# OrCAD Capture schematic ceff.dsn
size A; title: Discrete Negative Linear Regulator; rev: 1.0; note: PROJ-001
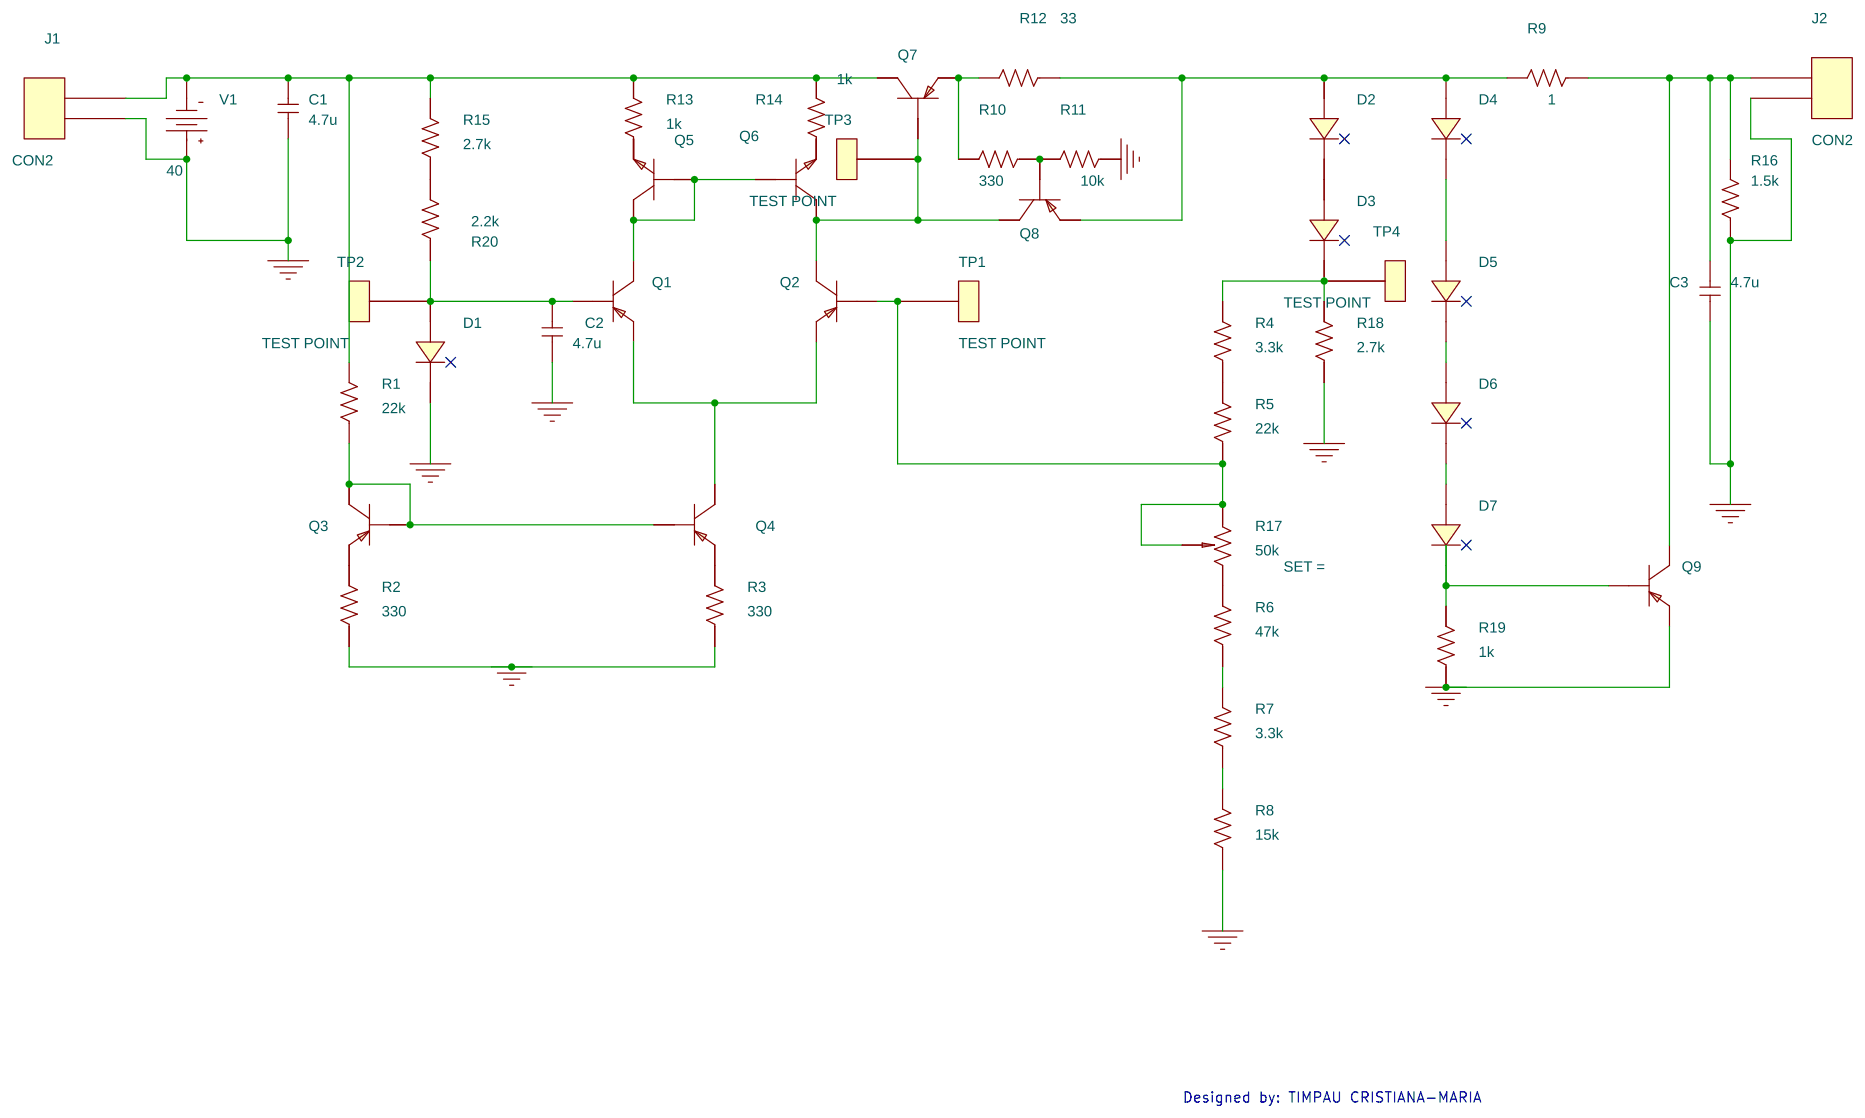
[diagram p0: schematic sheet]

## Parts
C1  4.7u  [CAPC2008X126N_0805]
C2  4.7u  [CAPC2008X126N_0805]
C3  4.7u  [CAPC2008X126N_0805]
D1  BZX84-C10  [TO236AA]
D2  BZX84-C10  [TO236AA]
D3  BZX84-C10  [TO236AA]
D4  BZX84-C6V8  [TO236AA]
D5  BZX84-C10  [TO236AA]
D6  BZX84-C10  [TO236AA]
D7  BZX84-C10  [TO236AA]
J1  CON2  [CONNECTOR]
J2  CON2  [CONNECTOR]
Q1  QBC807-25  [TO236AA]
Q2  QBC807-25  [TO236AA]
Q3  QBC807-25  [TO236AA]
Q4  QBC807-25  [TO236AA]
Q5  QBC817-25  [TO236AA]
Q6  QBC817-25  [TO236AA]
Q7  QMJD32CT4G  [DPACK]
Q8  QBC807-25  [TO236AA]
Q9  QMJD32CT4G  [DPACK]
R1  22k  [RES2012X50N_0805]
R2  330  [RES2012X50N_0805]
R3  330  [RES2012X50N_0805]
R4  3.3k  [RES2012X50N_0805]
R5  22k  [RES2012X50N_0805]
R6  47k  [RES2012X50N_0805]
R7  3.3k  [RES2012X50N_0805]
R8  15k  [RES2012X50N_0805]
R9  1  [RES2012X50N_0805]
R10  330  [RES2012X50N_0805]
R11  10k  [RES2012X50N_0805]
R12  33  [RES2012X50N_0805]
R13  1k  [RES2012X50N_0805]
R14  1k  [RES2012X50N_0805]
R15  2.7k  [RES2012X50N_0805]
R16  1.5k  [JUMPER2]
R17  50k  [TS53YL]
R18  2.7k  [RES2012X50N_0805]
R19  1k  [RES2012X50N_0805]
R20  2.2k  [RES2012X50N_0805]
TP1  TEST POINT  [tpnou]
TP2  TEST POINT  [tpnou]
TP3  TEST POINT  [tpnou]
TP4  TEST POINT  [tpnou]
V1  VDC

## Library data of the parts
C1-C3 = C
D1-D3 D5-D7 = BZX84-C10_5
D4 = BZX84-C6V8_3
J1 J2 = CON2
Q1-Q4 Q8 = QBC807-25_0
Q5 Q6 = QBC817-25_0
Q7 Q9 = QMJD32CT4G
R1-R16 R18-R20 = R
R17 = POT
TP1-TP4 = TEST_POINT_0
V1 = VDC: DC: 40

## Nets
0: C1.1 C2.1 C3.1 D1.3(C) J1.2 J2.2 Q9.1(E) R2.1 R3.1 R8.1 R11.1 R16.1 R18.1 R19.1 V1.0(+)
N13323: Q1.3(C) Q5.1(B) Q5.3(C) Q6.1(B)
N13331: Q2.3(C) Q6.3(C) Q7.2(B) Q8.3(C) TP3.1
N13335: Q1.2(E) Q2.2(E) Q4.3(C)
N13367: Q7.1(E) R10.2 R12.2
N13401: D2.1(A) D4.1(A) Q8.2(E) R9.2 R12.1
N13657: C1.2 J1.1 Q7.3(C) R1.2 R13.2 R14.2 R15.2 V1.1(-)
N13911: Q6.2(E) R14.1
N13917: Q5.2(E) R13.1
N15099: Q3.1(B) Q3.3(C) Q4.1(B) R1.1
N25936: C3.2 J2.1 Q9.3(C) R9.1 R16.2
N26188: D7.3(C) Q9.2(B) R19.2
N28749: Q2.1(B) R5.1 R17.1 R17.2(t) TP1.1
N30043: C2.2 D1.1(A) Q1.1(B) R20.1 TP2.1
N72258: D3.3(C) R4.2 R18.2 TP4.1
N77501: D4.3(C) D5.1(A)
N77505: D5.3(C) D6.1(A)
N77509: D6.3(C) D7.1(A)
N85916: R6.1 R7.2
N85976: R7.1 R8.2
N101707: Q3.2(E) R2.2
N101708: Q8.1(B) R10.1 R11.2
N101710: R6.2 R17.3(2)
N101712: Q4.2(E) R3.2
N101713: D2.3(C) D3.1(A)
N101760: R15.1 R20.2
N102298: R4.1 R5.2

Not connected (* = marked no-connect by the designer): D1 2(B)*; D2 2(B)*; D3 2(B)*; D4 2(B)*; D5 2(B)*; D6 2(B)*; D7 2(B)*

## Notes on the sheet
- Designed by: TIMPAU CRISTIANA-MARIA
